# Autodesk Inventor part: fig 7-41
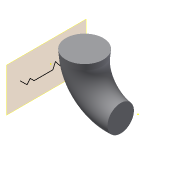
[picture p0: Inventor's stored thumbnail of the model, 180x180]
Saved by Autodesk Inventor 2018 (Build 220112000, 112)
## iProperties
Created: 2011-07
Part Number: fig 7-41
Material: Generic
Document SubType Name: Modeling
Designer: CadCim
Density: 1 g/cm^3
Appearance: Default
Author: CadCim
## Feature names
1. Sweep1
## Parameters: d0 = 5 deg, d1 = -14.75 mm, d2 = 0
